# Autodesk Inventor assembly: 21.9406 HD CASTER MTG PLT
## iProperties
Created: 2010-11
Part Number: 21.9406 HD CASTER MTG PLT
Document SubType Name: Assembly
Designer: Administrator
Mass: 933.726 g
Surface Area: 541.218 cm^2
Volume: 331.813 cm^3
Density: 2.81401 g/cm^3
Author: Administrator
